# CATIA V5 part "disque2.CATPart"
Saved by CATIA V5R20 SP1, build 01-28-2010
Part number: disque1
Bounding box of the stored display mesh (mm): x 57.5 to 102.5, y 0 to 5, z 77.5 to 122.5
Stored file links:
  E:\EDELI\gcausse\Edeli_2012_190_gcausse\disque2.CATPart
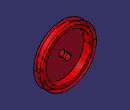
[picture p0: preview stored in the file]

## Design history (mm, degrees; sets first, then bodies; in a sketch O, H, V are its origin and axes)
Body1 (main body)
  DatumSurface1
  Sketch1 on face of DatumSurface1, origin (0, 5, 0), H (1, 0, 0), V (0, 0, 1)
    circle A1 centre (80, 100) radius 17.5
    circle A2 centre (80, 100) radius 2.5
    radius A1 = 17.5
    radius A2 = 2.5
  Pad1: profile Sketch1, direction (0, -1, 0), length 5
Body2
  Sketch2 on start face of Pad1, origin (0, 5, 0), H (-1, 0, 0), V (0, 0, 1)
    circle A1 centre (-80, 100) radius 20
    circle A2 centre (-80, 100) radius 17.5
    radius A2 = 17.5
    radius A1 = 20
  Pad2: profile Sketch2, direction (0, -1, 0), length 5
  Sketch3 on start face of Pad1, origin (0, 5, 0), H (-1, 0, 0), V (0, 0, 1)
Body3
  Sketch4 on start face of Pad1, origin (0, 5, 0), H (-1, 0, 0), V (0, 0, 1)
    circle A1 centre (-80, 100) radius 22.5
    circle A2 centre (-80, 100) radius 20
    radius A2 = 20
    radius A1 = 22.5
  Pad3: profile Sketch4, direction (0, -1, 0), length 5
